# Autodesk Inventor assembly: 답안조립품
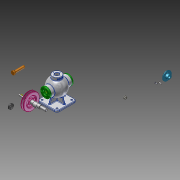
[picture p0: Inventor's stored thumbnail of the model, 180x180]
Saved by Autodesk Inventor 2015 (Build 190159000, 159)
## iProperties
Created: 2025-08
Part Number: 답안조립품
Document SubType Name: Assembly
Designer: user
Author: user
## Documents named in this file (15)
- C:\Users\user\Desktop\750808V1011\답안조립품.iam
- C:\Users\user\Desktop\750808V1011\본체.ipt
- C:\Users\user\Desktop\750808V1011\가져온 구성요소\V-벨트풀리\V-벨트풀리.ipt
- C:\Users\user\Desktop\750808V1011\가져온 구성요소\너트 M8\너트 M8.ipt
- C:\Users\user\Desktop\750808V1011\가져온 구성요소\뒤커버\뒤커버.ipt
- C:\Users\user\Desktop\750808V1011\가져온 구성요소\베어링- 6202\베어링- 6202.ipt
- C:\Users\user\Desktop\750808V1011\가져온 구성요소\볼트 M4 x 12\볼트 M4 x 12.ipt
- C:\Users\user\Desktop\750808V1011\가져온 구성요소\볼트 M4 x 16\볼트 M4 x 16.ipt
- C:\Users\user\Desktop\750808V1011\가져온 구성요소\상부커버\상부커버.ipt
- C:\Users\user\Desktop\750808V1011\가져온 구성요소\슬라이드\슬라이드.ipt
- C:\Users\user\Desktop\750808V1011\가져온 구성요소\앞커버\앞커버.ipt
- C:\Users\user\Desktop\750808V1011\가져온 구성요소\오일실 15 30 7\오일실 15 30 7.ipt
- C:\Users\user\Desktop\750808V1011\가져온 구성요소\칼라\칼라.ipt
- C:\Users\user\Desktop\750808V1011\가져온 구성요소\키 4 x 4 x 12\키 4 x 4 x 12.ipt
- C:\Users\user\Desktop\750808V1011\가져온 구성요소\편심축\편심축.ipt
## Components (1 placed, 1 different names)
1. V-벨트풀리:1
